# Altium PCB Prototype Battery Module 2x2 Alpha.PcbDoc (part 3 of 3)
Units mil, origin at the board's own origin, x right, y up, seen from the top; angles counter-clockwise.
Board outline 659.45 x 1614.17 mil, 6 copper layers (Component Side, Ground Plane (GND), Inner Layer 1, Inner Layer 2, Power Plane (VCC), Solder Side), stack 51.068 mil thick; 192 components, 101 nets, 859 pads, 497 vias.
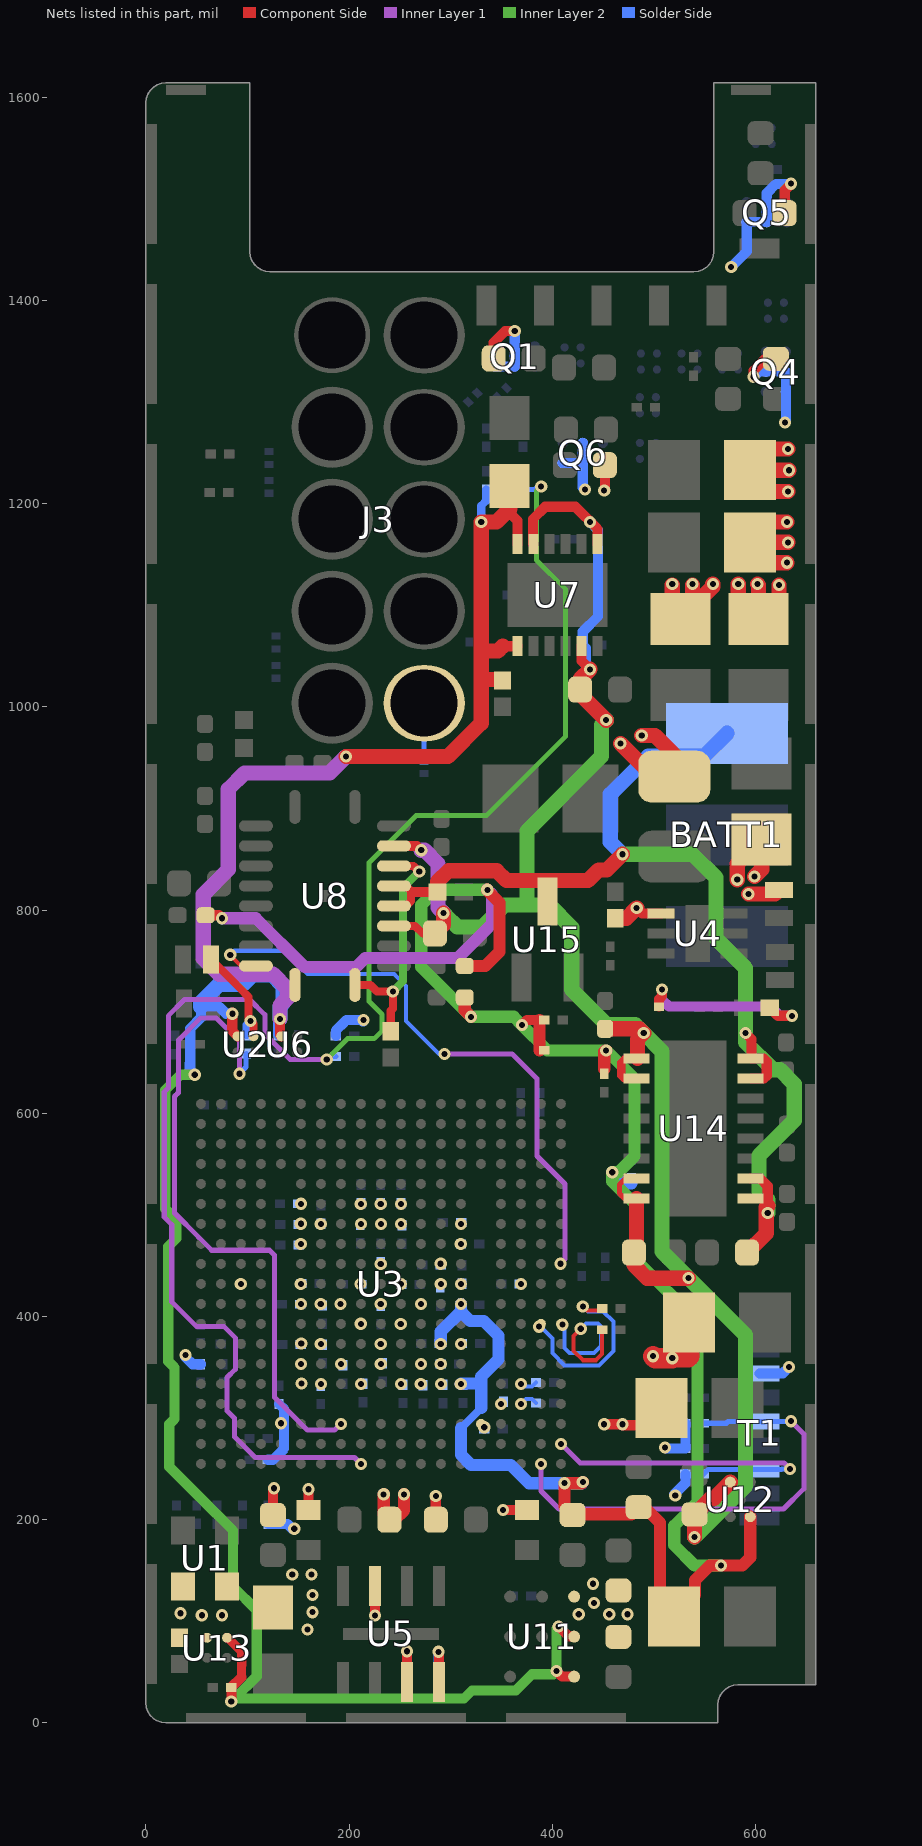
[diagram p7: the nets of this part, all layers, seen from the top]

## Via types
v1: diameter 12, hole 6, Component Side to Solder Side, tented both sides, 490 vias
v2: diameter 19.68, hole 10, Component Side to Solder Side, 6 vias
v3: diameter 12, hole 6, Component Side to Solder Side, 1 vias

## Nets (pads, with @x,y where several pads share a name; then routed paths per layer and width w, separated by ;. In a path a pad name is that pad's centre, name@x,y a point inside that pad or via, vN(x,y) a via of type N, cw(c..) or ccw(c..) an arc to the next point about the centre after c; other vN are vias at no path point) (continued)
TDO: R29.2 T1.6 U3.B1 | length 323
  Inner Layer 1 w5: v1(408.43,274.68) 427.11,256 628,256 v1(634,250)
  Solder Side w5: R29.2@549.06,245 553.62,249.57 625.57,249.57 625.57,249.43 626.13,250 v1(634,250)
TMS: R27.2 T1.4 U3.A2 | length 475.2
  Inner Layer 1 w5: v1(388.74,255) 388.74,228.26 406.5,210.5 511,210.5 ; 526.59,210.5 511,210.5 ; v1(635,297) 647.5,284.5 647.5,230.5 627.5,210.5 511,210.5
  Solder Side w5: R27.2@549.06,295 571.19,295 573,296.81 T1.4@604,296.81 634.81,296.81 v1(635,297)
TX_CLK_N: C86.2 U3.H2 | length 191.6
  Component Side w4: v1(430,410) 434,406 443,406 ; C86.2@444.95,406 443,406 ; C86.2@448.94,408 446.95,406 443,406
  Solder Side w4: v1(387,390) 388.38,390 400,378.38 400,364 412,352 446,352 460,366 460,395 450,405 436,405 435,405 v1(430,410)
TX_CLK_P: C85.2 U3.H1 | length 190.3
  Component Side w4: v1(428,388) 421,381 421,366 430,357 443,357 448.94,362.94 C85.2@448.94,387
  Solder Side w4: v1(410,392) 412,390 412,368.97 416.97,364 441.03,364 448,370.97 448,390.03 445.03,393 433,393 v1(428,388)
TX_N: C84.2 U3.E3 | length 17.7
  Solder Side w4: v1(369.06,333.74) 371.8,331 379.94,331 C84.2@383.94,335
TX_P: C83.2 U3.D3 | length 18.6
  Solder Side w4: v1(369.06,314.06) 374,319 379.95,319 C83.2@383.94,315
USBPG_N: U3.L1 U8.19 | length 599.1
  Component Side w4: v1@84.17,754.29 93.38,745.08 U8.19@108.26,745.08
  Inner Layer 1 w5: v1(294,658.51) 360.49,658.51 384.93,634.07 384.93,558 412.5,530.43 412.5,456.5 v1(408,452)
  Solder Side w4: v1(83,756) 87,760 136,760 159,737 244.38,737 256,725.38 256,718 256,691 288.49,658.51 v1(294,658.51)
V1P2: C1.2 C2.2 C18.2 C19.2 C20.2 C21.2 C22.2 C23.2 C24.2 C25.2 C27.2 C28.2 C29.2 C30.2 C33.2 C40.2 C41.2 C78.2 U3.E8 U3.E14 U3.F7 U3.G6 U3.G10 U3.G14 U3.H9 U3.H11 U3.J8 U3.J10 U3.J12 U3.K9 U3.K11 U3.L10 U3.M6 U3.N9 U3.N10 U3.N11 U3.N14 U3.P9 U3.P10 U3.P11 U11.A1 | length 71.1
  Component Side w10: U3.E14@152.52,333.74 152.74,333.74 v1(153,334)
  Component Side w20: v1(499,361) 501,359 v1(518,359) 519,360 534,360 534.6,360.6 C78.2@534.6,394
  other v1: 426,107 456,107 474,107 441,118 440,137 270.55,333.48 290.19,353.35 152.89,373.49 231.09,372.94 310,373.03 211.5,392.84 250.82,392.72 191.63,412.4 231.14,412.44 270.59,412.44 211.24,432.09 250.95,432.09 231.09,451.86 309.91,471.44 152.44,491.29 211.57,491.22 231.26,491.22 250.94,491.22 211.5,510.84 231.09,510.91 250.98,510.83
V2P5: C59.2 C63.2 C64.2 C65.2 C82.2 L5.2 R38.1 R40.1 R42.1 R50.1 R51.1 R53.1 R54.1 U3.E6 U3.G7 U3.J6 U12.C3 | length 2340.7
  Component Side w10: R38.1@58.78,795 72,795 v1(75,792) ; v1(370,687) 375,692 R51.1@387.22,692
  Component Side w12: R42.1@313.78,714 313.78,701.22 v1(320,695) ; R40.1@313.78,745 334,745 348,759 348,807.27 336,819.27 v1(336,820) ; R50.1@387.22,662 R51.1@387.22,692 ; C59.2@420,204.69 412,212.69 v1(412,236) 429,236 v1(430,237) ; C59.2@420.67,205.35 478.04,205.35 C82.2@485,212.31 490.69,212.31 506,197 506,118.6 L5.2@519.6,105 540.5,125.9 540.5,140.5 555,155 v1(566,155) 587,155 594.84,162.84 U12.C3@594.84,202.95 ; R54.1@451,643.78 451,660.64 452.36,662 v1(453,662)
  Inner Layer 1 w12: v1(75,792) 108,792 156,744 207,744 215.82,752.82 306.82,752.82 340.69,786.68 340.69,815.32 v1(336,820)
  Inner Layer 2 w12: v1(336,820) 286,820 271,805 271,744 v1(320,695) 362,695 v1(370,687) 395,662 v1(453,662) 481,634 481,557.96 465.04,542 v1(459,542) 459,533 483,509 483,455 543,395 543,359 ; 520,182.91 520,175 ; 543,387 543,359 ; v1(566,155) 540,155 520,175 ; 520,175 520,194 543,217 543,359
  Solder Side w8: 310,290 330,310
  Solder Side w12: v1(290.19,373.03) 290.19,385.18 310.06,405.06 ; v1(309.92,333.61) 310.31,334 330,334 ; 310,290 310,264 320,254 359,254 377,236 v1(412,236) v1@429,236 ; v1(310.06,412.4) 310.06,405.06 ; 330,310 330,334 ; v1(459,542) 469.78,531.22 R53.1@478,531.22 ; 310.06,405.06 312.11,403 312.11,402.63 319.22,395.52 332.52,395.52 347,381.04 347,358 330,341 330,334
V3P3: C3.2 C4.2 C5.2 C6.2 C7.2 C9.2 C12.1 C13.1 C15.1 C16.2 C17.1 C26.2 C34.2 C35.2 C36.2 C37.2 C38.2 C44.2 C51.2 C57.2 C58.2 C60.2 C61.2 C62.2 C66.2 C67.2 C68.2 C69.2 C70.2 C71.2 C72.2 C73.2 C95.2 L2.1 R22.1 R26.2 R27.1 R28.1 R29.1 R34.2 T1.2 U1.1 U1.4 U3.C5 U3.C15 U3.D4 U3.E7 U3.E9 U3.E11 U3.E13 U3.F8 U3.F10 U3.F12 U3.F14 U3.G13 U3.J13 U3.J14 U3.K3 U3.K6 U3.K7 U3.K14 U3.K17 U3.L7 U3.M14 U3.N6 U3.N13 U3.P14 U4.4 U5.3 U5.7 U5.8 U13.A1 | length 788.9
  Component Side w10: C60.2@125,204.69 125,231 v1(126,231) ; U3.C15@132.83,294.37 132.83,294.83 v1(133,295) ; C16.2@160,209.68 v1(160,230) ; v1(225.39,105.61) U5.3@225.39,134.84 ; U5.7@256.89,40.35 v1(256.89,70.58) ; C72.2@285.31,200 v1(285.31,223.31) ; v1(288,70) 288.39,69.61 U5.8@288.39,40.35 ; v1(351.32,209.68) C37.2@375,209.68 ; v1(451,294) v1(469,294) 469,293 490.6,293 C38.2@507.6,310 ; v1(483,802) 488.32,796.68 U4.4@507.17,796.68
  Component Side w12: v1(234,225) 234,205.69 C61.2@239.69,200 245,200 254,209 v1(254,225)
  Component Side w15: C9.2@462,792.01 473.01,792.01 v1(483,802) ; v1(467,964) 499.63,931.37 L2.1@520,931.37 520,953 501,972 v1(488,972)
  Solder Side w10: v1(39,362) 39,360 45.94,353.06 R34.2@54,353.06 ; R26.2@120,195.94 139.06,195.94 143.84,191.16 v1(146,191.16) ; R22.1@120.06,259 125,259 136,270 136,308.94 C34.2@131,313.94 ; C3.2@186.94,676 186.94,681.48 ; 195.23,689.77 186.94,681.48 ; v1@213.34,690.33 214,690.33 v1(214,692) 197.46,692 186.94,681.48 ; v1(256.89,70.58) 257,70.47 C13.1@257,55.06 ; C12.1@288,55.06 v1(288,70) ; v1(511,271) 512,270 R28.1@530.94,270 R27.1@530.94,295 ; v1(521,224) 520,225 530.94,235.94 R29.1@530.94,245 ; T1.2@604,344.06 626.8,344.06 v1(633,350.25)
  other v1: 159,92 55,106 75,106 34,108 164,109 164,126 144,146 163,146 333,291 349.37,314.06 172.2,333.74 211.57,333.74 250.94,333.74 290.32,333.74 152.52,353.43 191.89,353.43 231.18,353.35 270.63,353.43 172.13,372.97 152.48,412.44 172.09,412.43 93.39,432.09 152.45,432.09 290.24,432.08 310.07,431.94 369.06,432.17 290.09,451.91 152.46,471.44 172.13,490.97 310.09,490.97 152.56,510.94
V3P3_ALWAYS: C32.2 C39.2 C52.2 C77.2 C94.2 R3.2 U2.A2 U6.A2 U7.1 U7.12 U11.A2 U11.A3 U13.A2 | length 2532.4
  Component Side w9: U13.A2@79.84,83.84 80.55,83.84 94.26,70.13 94.26,56.74 94,56.47 94,44.95
  Component Side w10: v1(84,21) 84.06,21.06 C94.2@84.06,35 94,44.95 ; v1@85,699 v1(85,698) 85,681 U2.A2@90.13,675.87 86,680 ; v1(132,693) 132,677 U6.A2@133.13,675.87 ; 351,1060 351.2,1059.8 U7.1@365.63,1059.8 ; C52.2@358,1217.54 358,1195 358,1191 365.63,1183.37 U7.12@365.63,1160.2 ; v1(404,51) 409.37,45.63 U11.A3@421.5,45.63 ; v1(406,95) 416,85 U11.A2@421.5,85
  Component Side w15: v1(197,951.2) 297.2,951.2 330,984 330,1027 ; C77.2@351,1025.99 349.99,1027 330,1027 ; 351.2,1059.8 346.39,1055 330,1055 ; 358,1195 345,1182 v1(330,1182) 330,1055 ; 330,1027 330,1055
  Inner Layer 1 w15: 114,737 102,737 ; v1(132,693) 132,706 139,713 139,723 125,737 102,737 ; v1(197,951.2) 180.81,935 97,935 81,919 81,840 56.5,815.5 56.5,752.5 72,737 102,737
  Inner Layer 2 w10: 19,597 19,584 ; 23.5,251.82 26,249.32 ; v1@45.99,638 v1(48,638) 34,638 19,623 19,584 ; 59.65,215.58 53.62,221.62 ; v1(84,21) v1@87,24 ; 109,72 109,46 ; v1(406,95) 404,93 v1(404,51) 401,48 380,48 364,32 321,32 313,24 v1@87,24 ; 19,584 19,506 30,495 30,477 22,469 22,356 28.02,349.98 28.02,299 23,293.98 23,252.23 53.62,221.62 ; 53.62,221.62 85.69,189.55 85.69,134.32 109,111 109,46 ; v1@87,24 109,46
  Solder Side w8: v1(330,1182) 330,1198 335,1203 R3.2@335,1213.94
  Solder Side w10: 43,649 43,643 ; v1(48,638) 43,643 ; v1(85,698) 79,698 72,705 C32.2@54.06,705 54.06,694.06 43.54,683.54 43.54,643.54 43,643 ; C39.2@130,677.06 v1@130,691 ; v1(132,693) v1@132,696.63
  Solder Side w15: C32.2@54.06,705 54.06,709.06 71.79,726.79 95.56,726.79 105.28,736.5 123.99,736.5 ; 128.25,732.25 123.99,736.5 ; v1(132,693) 132,705 135,708 135,725.49 123.99,736.5
V28P0: C8.2 C10.2 C11.2 C31.2 C49.2 C53.2 D1.2 Q1.2 Q1.3 Q1.6 Q4.2 Q4.3 Q4.6 Q5.2 Q5.3 Q5.6 Q6.2 Q6.3 Q6.6 R11.1 R13.1 R16.1 R17.1 R44.1 | length 1278.7
  Component Side w10: R11.1@342.32,1343 342.32,1358.65 353.67,1370 v1(363,1370) ; v1(451,1213) 451.69,1213.68 R17.1@451.69,1238 ; R13.1@504.94,705 504.94,712.32 508,715.37 v1(508,722) ; v1(598,1325) 598,1331 609.69,1342.68 R44.1@620,1342.68 ; C10.2@613.99,704 621.99,696 v1(636,696) ; R16.1@628.69,1486 628.69,1508.68 v1(635,1515)
  Component Side w15: v1@518,1119.97 518,1094.4 C31.2@526,1086.4 C31.2@538,1098.4 ; v1@538,1119.97 C31.2@538,1098.4 ; v1(558,1121) 558,1118.4 C31.2@538,1098.4 ; v1(582,830) 582,845.6 C49.2@606,869.6 606,840 v1(599,833) ; v1(583,1121) 583,1106.4 C53.2@603,1086.4 ; v1@597,816 v1(593,816) 619.22,816 D1.2@623,819.78 ; v1(602,1121) 603,1120 C53.2@603,1086.4 ; v1(623,1120) 623,1106.4 C53.2@603,1086.4 ; v1(631,1142) 614.4,1142 C8.2@594.4,1162 ; v1(631,1182) 605,1182 594.4,1171.4 C8.2@594.4,1162 ; v1(632,1162) C8.2@594.4,1162 ; v1(632,1212) 614,1212 594.4,1231.6 C11.2@594.4,1233 ; v1(632,1254) 615.4,1254 C11.2@594.4,1233 ; v1(633,1233) C11.2@594.4,1233
  Inner Layer 1 w10: v1(508,722) 508,712 515,705 615,705 ; 623,697 615,705 ; v1(636,696) 624,696 615,705
  Solder Side w10: Q1.2@343.32,1335.16 Q1.3@363,1335.16 363,1337 Q1.6@363,1354.84 363,1364 v1(363,1370) ; Q6.2@410.32,1240.16 Q6.3@430,1240.16 ; Q6.6@430,1259.84 Q6.3@430,1240.16 ; v1(432,1214) 430,1216 Q6.3@430,1240.16 ; v3(576,1433) 591.32,1448.32 Q5.2@591.32,1477.16 602,1477.16 Q5.3@611,1477.16 Q5.6@611,1496.84 611,1505.67 620,1514.67 634.67,1514.67 v1(635,1515) ; v1(598,1325) 603,1330 Q4.6@610.16,1330 Q4.3@629.84,1330 Q4.2@629.84,1310.32 629.84,1283.16 630,1283 630,1281 v1(628.98,1280.02) v1@629,1281
  other v1: 518,1121 538,1121
VBATT: BATT1.1 C46.2 C47.2 U8.5 U8.6 U14.1 U14.2 U14.7 U14.8 U15.3 | length 1141.3
  Component Side w8: U8.5@244.09,804.14 256.14,804.14 260.82,808.82 260.82,817 261.82,818 256,823.82 U8.6@244.09,823.82
  Component Side w10: 261.82,818 C46.2@287.01,818 ; v1(590,679) 596.1,672.9 596.1,653.9 608.1,653.9 611,651 611,637 608.21,634.21 U14.7@596.1,634.21 ; U14.2@595.1,535.79 604.59,535.79 612,528.37 612,509
  Component Side w15: C46.2@287.01,818 287.01,828.01 297.77,838.77 345.23,838.77 354.91,829.09 435.17,829.09 445.62,839.55 453.55,839.55 v1(469,855) ; C47.2@591.69,463 610.63,481.94 610.63,507.63 612,509
  Inner Layer 2 w15: v1(469,855) 538,855 561,832 561,772 590,743 v1(590,679) 590,670 617,643 624,643 638,629 638,593 603.5,558.5 603.5,523.5 612,515 v1(612,502)
  Solder Side w15: v1(469,855) 457,867 457,914 494.5,951.5 549.31,951.5 BATT1.1@571.81,974
VCONN: C42.2 C48.2 C50.2 C81.2 J3.1 R39.1 R49.1 TVS9.1 U7.5 U7.7 U7.11 U8.4 U8.8 U12.A1 U14.9 U14.10 U14.15 U14.16 | length 2085.3
  Component Side w5: U14.16@482.9,516.1 470.9,516.1 466,521 466,529.91 471.88,535.79 U14.15@482.9,535.79
  Component Side w8: U8.4@244.09,784.45 265,784.45 272.45,777 C42.2@284.31,777 ; 468,650 467.87,649.87 ; U14.10@482.9,634.21 470.79,634.21 467.87,637.13 467.87,649.87 ; U14.9@482.9,653.9 471.9,653.9 467.87,649.87
  Component Side w10: U8.8@244.09,863.19 266.81,863.19 v1(271,859) ; U7.11@381.38,1160.2 381,1160.57 381,1185.05 392.95,1197 422.63,1197 444.37,1175.26 U7.7@444.37,1160.2 ; C50.2@427.31,1017 C50.2@428.62,1018.31 ; U7.5@428.62,1059.8 428.62,1045.38 v1(437,1037)
  Component Side w15: C42.2@284.77,777 C42.2@284.31,777 293,785.69 v1(293,797) ; v1(437,1037) 427.31,1027.31 C50.2@427.31,1017 427.31,1012.69 v1(453,987) ; R49.1@452,683.22 485.78,683.22 v1(490,679) 483.9,672.9 U14.9@483.9,653.9 ; U14.16@482.9,516.1 482.9,465.58 C48.2@480.31,463 480.31,450.69 493.3,437.7 519,437.7 ; 506.16,437.7 519,437.7 ; v1(534,438) 533.51,438 533.21,437.7 519,437.7 ; v1(540,183) C81.2@540,205.31 555.84,221.16 559.27,221.16 U12.A1@575.16,237.05
  Inner Layer 1 w15: v1(271,859) 274.16,859 287.5,845.66 287.5,802.5 v1(293,797)
  Inner Layer 2 w15: v1@294.58,795.42 306.5,783.5 331.35,783.5 ; 316.02,783.5 331.35,783.5 ; 336.42,788.58 331.35,783.5 ; 419,767.5 419,738 ; v1(453,987) 448.5,982.5 448.5,951.5 375,878 375,805 ; v1(540,183) 590,233 590,382 v1(534,438) 508,464 508,661 v1(490,679) 481.5,687.5 453.5,687.5 419,722 419,738 ; 331.35,783.5 352.85,805 375,805 ; 375,805 397,805 419,783 419,738
  Solder Side w5: TVS9.1@273.86,946.14 J3.1@273.86,1003.7
  Solder Side w10: v1(437,1037) 432.94,1041.06 432.94,1058.01 R39.1@429.94,1061 429.94,1073.94 445,1089 445,1174 v1(437,1182)
VLDO: C45.2 U8.1 U8.7 | length 232.9
  Component Side w8: U8.1@205.71,726.38 221,726.38 227.38,720 v1(243,720) 243,703 ; C45.2@241,680.99 241,701 ; U8.7@244.09,843.51 263.49,843.51 v1(269,838)
  Inner Layer 2 w8: v1(243,720) 253,730 253,822 v1(269,838)
VUSB: U8.20
WAKE_RX: R7.2 U3.C12 | length 683.1
  Inner Layer 1 w5: 28,616 28,606 ; 30.59,619.06 32,620.47 32,646 ; 31.76,620.24 28,616.47 28,606 ; 32,641.77 32,646 ; 58.46,471.54 52,478 ; 70,693 91,672 ; 74.21,688.79 69,694 62,694 54,694 32,672 32,646 ; 86.37,676.63 92,671 v1(92,639) ; v1(191.89,294.37) 185.7,288.18 158.91,288.18 126.65,320.44 126.65,460.35 121.73,465.27 64.73,465.27 52,478 ; 28,606 28,600 28,594 28,502 52,478
  Solder Side w5: v1(92,639) 98.5,645.5 98.5,651 ; 98.5,647.5 98.5,651 ; R7.2@99,658.94 98.5,658.45 98.5,651
WAKE_RX_PWR: D3.1 R7.1 U2.B2 | length 111.5
  Component Side w8: D3.1@63.98,751.61 92.87,722.72 101,714.59 v1@101,693 ; v1(103,691) v1@101,693 ; U2.B2@105.87,675.87 105.87,688.13 v1@101,693
  Solder Side w8: R7.1@99,677.06 99,683 99,687 v1(103,691)
WAKE_TX: R2.2 R4.2 U3.A11 | length 1613.3
  Inner Layer 1 w5: 19.5,496.36 18,497.86 ; 57,712 38,712 ; 117,687 117,684 ; v1@177.04,653.04 v1(178,653.04) 141.96,653.04 117,678 117,684 ; v1(211.57,255) 205.39,261.18 107.67,261.18 87.2,281.66 87.2,299.88 79.89,307.2 79.89,339.89 88,348 88,379 77,390 50,390 25.43,414.57 25.43,490.43 18,497.86 ; 18,497.86 18,621 22,625 22,696 38,712 ; 38,712 102,712 117,697 117,684
  Inner Layer 2 w5: v1@178.46,653.5 v1(178,653.04) 198.46,673.5 219,673.5 ; 215.5,673.5 219,673.5 ; v1(389,1217) 384.5,1212.5 384.5,1144.5 413.15,1115.85 413.15,1048 ; 413.15,1035.85 413.15,1048 ; 219,673.5 224.59,673.5 232.5,681.41 232.5,697.27 219.5,710.27 219.5,846.64 265.86,893 335,893 413.15,971.15 413.15,1048
  Solder Side w5: v1(178,653.04) 180.96,656 R2.2@186.94,656 ; R4.2@371,1213.94 382.94,1213.94 386,1217 v1(389,1217)
pads on no net: U3.A3 U3.A4 U3.A5 U3.A6 U3.A7 U3.A8 U3.A9 U3.A12 U3.A13 U3.A14 U3.A15 U3.A16 U3.A17 U3.B3 U3.B4 U3.B5 U3.B6 U3.B7 U3.B8 U3.B9 U3.B10 U3.B11 U3.B12 U3.B14 U3.B15 U3.B16 U3.B17 U3.C2 U3.C6 U3.C7 U3.C8 U3.C9 U3.C10 U3.C11 U3.C14 U3.D1 U3.D2 U3.D18 U3.E1 U3.E2 U3.E17 U3.E18 U3.F1 U3.F3 U3.F17 U3.F19 U3.G1 U3.G17 U3.H3 U3.H7 U3.H14 U3.H17 U3.H18 U3.H19 U3.J2 U3.J17 U3.J18 U3.K18 U3.L3 U3.L6 U3.L14 U3.L18 U3.L19 U3.M7 U3.M13 U3.M17 U3.M18 U3.M19 U3.N17 U3.N19 U3.P3 U3.P6 U3.R1 U3.R2 U3.R3 U3.T1 U3.T2 U3.T3 U3.T10 U3.T19 U3.U1 U3.U2 U3.U10 U3.U18 U3.U19 U3.V1 U3.V2 U3.V6 U3.V7 U3.V8 U3.V9 U3.V12 U3.V13 U3.V14 U3.V15 U3.W2 U3.W5 U3.W6 U3.W8 U3.W9 U3.W11 U3.W12 U3.W14 U3.W15 U4.2 U4.5 U7.8

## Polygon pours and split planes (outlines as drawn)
V1P2 on Component Side "TopLayer-No Net" (solid, remove dead copper, pour order 17): 514,424 560,424 562,422 562,385 562,367 558,363 544,349 509,349 496,349 489,356 488,357 488,369 488,370 490,372 492,374 504,374 505,374 510,379 510,408 510,420 514,424
GND on Component Side "TopLayer-No Net" (solid, remove dead copper, pour order 16): 587,445 624,445 631,438 631,401 631,368 624,361 612,349 612,302 612,284 607,279 559,279 557,279 555,281 554,282 554,344 568,358 575,365 575,376 575,438 579,442 582,445 587,445
V3P3 on Component Side "TopLayer-No Net" (solid, remove dead copper, pour order 15): 475,342 507,342 531,342 535,338 535,297 535,283 532,280 531,279 469,279 451,279 443,287 441,289 441,305 441,321 448,328 462,342 475,342
V1P2 on Component Side "Mechanical 1-No Net" (solid, pour order 14): 415,116 415,104 419,100 420,99 439,99 444,94 444,84 444,78 449,73 481,73 485,77 485,138 481,142 478,145 422,145 418,145 415,142 415,116
GND on Component Side "Mechanical 1-No Net" (solid, pour order 13): 105,68 109,72 155,72 166,72 171,67 171,28 166,23 106,23 104,25 104,67 105,68
GND on Component Side "Mechanical 1-No Net" (solid, pour order 12): 336,31 365,31 372,38 372,111 372,149 380,157 402,157 407,157 410,154 472,154 477,159 481,163 481,183 476,188 456,188 442,188 434,180 433,179 412,179 356,179 350,173 334,157 334,112 334,33 336,31
V3P3 on Component Side "Top Solder-No Net" (solid, remove dead copper, pour order 11): 68,76 66,74 23,74 23,148 26,151 169,151 175,145 175,93 167,85 110,85 102,93 99,96 81,96 73,96 68,91
V1P2 on Inner Layer 2 "TopLayer-No Net" (solid, remove dead copper, pour order 18): 393,525 525.09,392.91 525.09,99.21 517.6,91.72 416.28,91.72 308,200 261,200 120,341 120,489 156,525
VCONN on Inner Layer 1 "Inner Layer 1-No Net" (solid, pour order 10): 230,963 230,1026 251,1047 372,1047 400,1075 456,1075 494,1037 494,945 492,945 474,927 445,898 399,898 388,898 350,936 344,942 264,942 251,942 230,963
GND on Ground Plane (GND) (split plane): 649.36,47.49 582.68,47.49 582.11,47.41 581.55,47.42 577.17,46.93 576.07,46.66 574.97,46.43 570.8,44.97 569.8,44.46 568.77,43.99 565.04,41.65 564.17,40.93 563.27,40.24 560.15,37.12 559.47,36.23 558.75,35.36 556.4,31.62 555.93,30.6 555.42,29.59 553.97,25.43 553.73,24.32 553.46,23.23 552.97,18.85 552.98,18.28 552.91,17.72 552.91,10.09 20.25,10.09 17.56,10.39 15.55,11.09 13.74,12.23 12.23,13.74 11.09,15.55 10.39,17.56 10.09,20.25 10.09,1593.92 10.39,1596.61 11.09,1598.62 12.23,1600.43 13.74,1601.94 15.55,1603.08 17.56,1603.78 20.25,1604.09 92.28,1604.09 92.28,1448.03 92.35,1447.47 92.34,1446.9 92.83,1442.52 93.1,1441.43 93.34,1440.32 94.79,1436.16 95.3,1435.15 95.77,1434.12 98.12,1430.39 98.84,1429.52 99.52,1428.63 102.64,1425.51 103.54,1424.82 104.41,1424.1 108.14,1421.76 109.17,1421.28 110.18,1420.78 114.34,1419.32 115.44,1419.09 116.54,1418.82 120.92,1418.32 121.48,1418.33 122.05,1418.26 539.37,1418.26 539.93,1418.33 540.5,1418.32 544.88,1418.82 545.98,1419.09 547.08,1419.32 551.24,1420.78 552.25,1421.28 553.28,1421.76 557.01,1424.1 557.88,1424.82 558.78,1425.51 561.89,1428.63 562.58,1429.52 563.3,1430.39 565.65,1434.12 566.12,1435.15 566.63,1436.16 568.08,1440.32 568.31,1441.42 568.58,1442.52 569.08,1446.9 569.07,1447.47 569.14,1448.03 569.14,1604.09 649.36,1604.09
V28P0 on Power Plane (VCC) (split plane): 649.36,684.97 648.45,685.09 559.18,685.09 494.99,749.27 495.09,750 495.09,755.82 517.13,777.87 518.74,779.96 519.74,782.39 520.09,785 520.09,795 520.09,980 519.74,982.61 518.74,985.04 517.13,987.13 445.09,1059.18 445.09,1135 444.74,1137.61 443.74,1140.04 442.13,1142.13 400.09,1184.18 400.09,1280 399.74,1282.61 399.24,1283.83 398.74,1285.04 397.13,1287.13 335.09,1349.18 335.09,1355 334.74,1357.61 334.09,1359.2 334.09,1418.26 539.37,1418.26 539.93,1418.33 540.5,1418.32 544.88,1418.82 545.98,1419.09 547.08,1419.32 551.24,1420.78 552.25,1421.28 553.28,1421.76 557.01,1424.1 557.88,1424.82 558.78,1425.51 561.89,1428.63 562.58,1429.52 563.3,1430.39 565.65,1434.12 566.12,1435.15 566.63,1436.16 568.08,1440.32 568.31,1441.42 568.58,1442.52 569.08,1446.9 569.07,1447.47 569.14,1448.03 569.14,1604.09 649.36,1604.09
V3P3 on Power Plane (VCC) (split plane): 92.28,1448.03 92.35,1447.47 92.34,1446.9 92.83,1442.52 93.1,1441.43 93.34,1440.32 94.79,1436.16 95.3,1435.15 95.77,1434.12 98.12,1430.39 98.84,1429.52 99.52,1428.63 102.64,1425.51 103.54,1424.82 104.41,1424.1 108.14,1421.76 109.17,1421.28 110.18,1420.78 114.34,1419.32 115.44,1419.09 116.54,1418.82 120.92,1418.32 121.48,1418.33 122.05,1418.26 313.91,1418.26 313.91,1346 314.26,1343.39 315.27,1340.96 316.87,1338.87 317.43,1338.43 317.87,1337.87 379.91,1275.82 379.91,1180 380.26,1177.39 381.27,1174.96 382.87,1172.87 424.91,1130.82 424.91,1055 425.26,1052.39 426.27,1049.96 427.87,1047.87 499.91,975.82 499.91,795 499.91,789.18 487.87,777.13 479.83,769.1 478.96,768.74 476.87,767.13 475.27,765.04 474.26,762.61 473.91,760 473.91,746 474.26,743.39 475.27,740.96 476.87,738.87 547.87,667.87 549.96,666.26 550.67,665.97 552.39,665.26 555,664.91 644.27,664.91 649.36,659.82 649.36,47.49 582.68,47.49 582.11,47.41 581.55,47.42 577.17,46.93 576.07,46.66 574.97,46.43 570.8,44.97 569.8,44.46 568.77,43.99 565.04,41.65 564.17,40.93 563.27,40.24 560.15,37.12 559.47,36.23 558.75,35.36 556.4,31.62 555.93,30.6 555.42,29.59 553.97,25.43 553.73,24.32 553.46,23.23 552.97,18.85 552.98,18.28 552.91,17.72 552.91,10.09 20.25,10.09 17.56,10.39 15.55,11.09 13.74,12.23 12.23,13.74 11.09,15.55 10.39,17.56 10.09,20.25 10.09,1593.92 10.39,1596.61 11.09,1598.62 12.23,1600.43 13.74,1601.94 15.55,1603.08 17.56,1603.78 20.25,1604.09 92.28,1604.09

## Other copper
Component Side:
  text "Top" at 177.17,-433.07 h60
Inner Layer 1:
  text "SIG1_LAYER3" at 0,-413.39 h60
Inner Layer 2:
  text "SIG2_LAYER4" at -39.37,-393.7 h60
Solder Side:
  text "Bottom" at 137.8,-452.76 h60
Ground Plane (GND) (plane layer: these items are gaps in the copper):
  text "GND_LAYER2" at -39.37,-374.02 h60
Power Plane (VCC) (plane layer: these items are gaps in the copper):
  lines w20: 324,1346 324,1428.35 ; 325,1355 325,1345 390,1280 390,1180 435,1135 435,1055 510,980 510,795 510,785 ; 484,760 484,746 555,675 648.45,675 658.45,665 ; 485,750 485,760 510,785 ; 495,770 510,785
  text "PWR_LAYER5" at -19.68,-433.07 h60

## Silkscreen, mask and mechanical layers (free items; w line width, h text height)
Top Overlay:
  text "Bat Module" at 66,1302 h30 r90
  text "M" at 107,1079 h100 r90
  text "K" at 599,819 h8
  text "A" at 595,786 h14
  text "K" at 34,769 h8
  text "K" at 597,756 h8
  text "A" at 76,734 h14
  text "A" at 595,722 h14
  text "A" at 78,708 h14
  text "K" at 15,679 h8
  text "Top Overlay" at -19.68,-433.07 h14
Bottom Overlay:
  text "(C) Motorola 2014" at 43,1584 h30 r90
  text "+" at 414,985 h30 r90
  text "-" at 414,889.5 h30 r90
  text "T" at 414,794 h30 r90
  text "Bottom Overlay" at -118.11,-433.07 h60
Top Paste:
  text "Top Paste" at -39.37,-413.39 h60
Bottom Paste:
  text "Bottom Paste" at -59.06,-433.07 h60
Top Solder:
  text "Top Solder" at 0,-374.02 h60
Bottom Solder:
  text "Bottom Solder" at -59.06,-452.76 h60
DIMENSION:
  lines w1: -0.01,19.69 ccw(c19.68,19.69) 19.68,0.01 ; 102.35,1450.4 ccw(c122.04,1450.4) 122.04,1430.72 ; 489.36,1430.72 ccw(c489.36,1450.4) 509.05,1450.4 ; 512.98,17.72 cw(c532.67,17.72) 532.67,37.41
OUTLINE:
  lines w1: 539.32,1428.32 ccw(c539.32,1448) 559,1448 ; 539.44,1428.35 122.04,1428.35 cw(c122.04,1448.03) 102.35,1448.03 102.35,1614.18 19.68,1614.18 ccw(c19.68,1594.5) -0.01,1594.5 -0.01,19.69 ccw(c19.68,19.69) 19.68,0.01 562.99,0.01 562.99,17.72 cw(c582.68,17.72) 582.68,37.41 659.45,37.41 659.45,1614.17 559.06,1614.17 559.06,1448.03
Mechanical 4:
  region: 615.16,1603.35 574.8,1603.35 574.8,1613.19 615.16,1613.19
  region: 59.06,1603.35 18.7,1603.35 18.7,1613.19 59.06,1613.19
  region: 0.98,39.37 0.98,157.48 10.83,157.48 10.83,39.37
  region: 0.98,196.85 0.98,314.96 10.83,314.96 10.83,196.85
  region: 0.98,354.33 0.98,472.44 10.83,472.44 10.83,354.33
  region: 0.98,511.81 0.98,629.92 10.83,629.92 10.83,511.81
  region: 0.98,669.29 0.98,787.4 10.83,787.4 10.83,669.29
  region: 0.98,826.77 0.98,944.88 10.83,944.88 10.83,826.77
  region: 0.98,984.25 0.98,1102.36 10.83,1102.36 10.83,984.25
  region: 0.98,1141.73 0.98,1259.84 10.83,1259.84 10.83,1141.73
  region: 0.98,1299.21 0.98,1417.32 10.83,1417.32 10.83,1299.21
  region: 0.98,1456.69 0.98,1574.8 10.83,1574.8 10.83,1456.69
  region: 648.62,1456.69 648.62,1574.8 658.46,1574.8 658.46,1456.69
  region: 648.62,1299.21 648.62,1417.32 658.46,1417.32 658.46,1299.21
  region: 648.62,1141.73 648.62,1259.84 658.46,1259.84 658.46,1141.73
  region: 648.62,984.25 648.62,1102.36 658.46,1102.36 658.46,984.25
  region: 648.62,826.77 648.62,944.88 658.46,944.88 658.46,826.77
  region: 648.62,669.29 648.62,787.4 658.46,787.4 658.46,669.29
  region: 648.62,511.81 648.62,629.92 658.46,629.92 658.46,511.81
  region: 648.62,354.33 648.62,472.44 658.46,472.44 658.46,354.33
  region: 648.62,196.85 648.62,314.96 658.46,314.96 658.46,196.85
  region: 648.62,39.37 648.62,157.48 658.46,157.48 658.46,39.37
  region: 354.33,10.83 472.44,10.83 472.44,0.98 354.33,0.98
  region: 196.85,10.83 314.96,10.83 314.96,0.98 196.85,0.98
  region: 39.37,10.83 157.48,10.83 157.48,0.98 39.37,0.98
ASSY_TOP:
  text "ASSY TOP" at 11,-291 h60
ASSY_BOT:
  text "ASSY BOTTOM" at 611,-291 h60
Drill Drawing:
  lines w1: -87.31,0.01 -0.01,0.01 -0.01,-91.17 ; 102.35,1614.18 102.35,1658.11 ; 496.06,1428.35 708.66,1428.35 ; 559.05,1613.18 559.05,1653.17 ; 562.99,-43.92 562.99,0.01 ; 593.06,1614.17 708.66,1614.17 ; 609.44,37.41 658.9,37.41 ; 609.44,1614.18 634.78,1614.18 ; 650.69,37.4 737.99,37.4 ; 659.45,-8.49 659.45,37.41 ; -185.05,1712.61 -296.71,1712.61 -185.05,1712.61 ; -185.05,1712.61 2.41,1603.94 ; -185.05,1712.61 2.41,1603.94 ; -146.18,1661.63 -121.5,1704.21 ; -146.18,1661.63 2.41,1603.94 ; -146.18,1661.63 -121.5,1704.21 ; -146.18,1661.63 2.41,1603.94 ; -121.5,1704.21 2.41,1603.94 ; -121.5,1704.21 2.41,1603.94
  lines w6: -1014.47,2168.38 -1014.47,2921.66 cw(c-974.8,2921.66) -974.8,2961.33 1621.53,2961.33 cw(c1621.53,2927.33) 1655.53,2927.33 ; -1014.47,2170.33 ccw(c-980.47,2170.33) -980.47,2136.33 ; -984,2136.33 1611,2135.65 ; -955.69,2768.65 1594.31,2768.65 ; -951,2868 1599,2868 ; 1609.01,2135.65 ccw(c1609.01,2181.89) 1655.25,2181.89 ; 1655.53,2181.89 1655.53,2926.33
  text "6 Layers Stack Up" at -210,2893 h57
  text "FAB NOTES:" at 1947.32,2890.98 h60
  text "Layer" at -951,2828 h24
  text "Gerber" at -51,2828 h24
  text "Copper" at 609,2828 h24
  text "Dielectric" at 1109,2828 h24
  text "Name" at -951,2788 h24
  text "Document" at -51,2788 h24
  text "Thickness" at 609,2788 h24
  text "Material" at 1109,2788 h24
  text "1. Materials: Green clad, FR-4/Epoxy class,or equivalent.dielectric costant 4.2+/-0.2 ," at 2055,2745 h60
  text "Top Solder Mask" at -951,2708 h34
  text "(.GTS)" at -51,2708 h34
  text "0.5mil" at 749,2708 h34
  text "Solder Resist" at 1109,2708 h34
  text "Top" at -951,2628 h34
  text "(.GTL)" at -51,2628 h34
  text "1.58mil" at 469,2628 h34
  text "see cross section for board thickness, copper" at 2215,2625 h60
  text "3.5mil" at 749,2588 h34
  text "FR4" at 1109,2588 h34
  text "GND_IN2" at -951,2548 h34
  text "(.GP1)" at -51,2548 h34
  text "0.65mil" at 469,2548 h34
  text "2.5mil" at 749,2508 h34
  text "FR4" at 1109,2508 h34
  text "weight and layer structures." at 2215,2505 h60
  text "SIG1_IN3" at -951,2468 h34
  text "(.G1)" at -51,2468 h34
  text "0.65mil" at 469,2468 h34
  text "2.5mil" at 749,2428 h34
  text "FR4" at 1109,2428 h34
  text "SIG2_IN4" at -951,2388 h34
  text "(.G2)" at -51,2388 h34
  text "0.65mil" at 469,2388 h34
  text "2. Components on the top and bottom layers." at 2035,2385 h60
  text "2.5mil" at 749,2348 h34
  text "FR4" at 1109,2348 h34
  text "PWR_IN5" at -951,2308 h34
  text "(.GP2)" at -51,2308 h34
  text "0.65mil" at 469,2308 h34
  text "3.5mil" at 749,2268 h34
  text "FR4" at 1109,2268 h34
  text "3. Minimum signal trace width/spacing : 4/5 mils." at 2035,2265 h60
  text "Bottom" at -951,2228 h34
  text "(.GBL)" at -51,2228 h34
  text "1.58mil" at 469,2228 h34
  text "Bottom Solder Mask" at -951,2148 h34
  text "(.GBS)" at -51,2148 h34
  text "0.5mil" at 749,2148 h34
  text "Solder Resist" at 1109,2148 h34
  text "4. Drilling:" at 2035,2145 h60
  text "4.1  minimum hole size is 6 mils drill." at 2195,2025 h60
  text "Overall Thickness :21.26 mil+/-10%" at -435,2011 h50
  text "4.2  all plated holes are to be plated thru and with min .001 thick." at 2195,1905 h60
  text "4.3  all hole diameters are finished sizes." at 2195,1785 h60
  text "R0.5" at -429.14,1692.92 h31
  text "5X" at -500.01,1688.98 h31
  text "2.6" at 106.29,1681.11 h31 r90
  text "14.2" at 565.74,1680.11 h31 r90
  text "4.4  all holes to be +/-0.003 from true position unless" at 2195,1665 h60
  text "41" at 727,1599 h31
  text "otherwise specified for PTH, or +/-0.002 if it's NPTH." at 2415,1565 h60
  text "4.5  NC drill file has been supplied, see hole size table." at 2195,1445 h60
  text "36.28" at 712,1418 h31
  text "5. Front to back pattern shall register within .005\"." at 2035,1325 h60
  text "6. Layer to layer(pattern to pattern) registration to be +/-.005\"." at 2035,1205 h60
  text "7. Soldermask: Both sides of board, Liquid Photo Imageable, soldermask" at 2035,1085 h60
  text "over bare copper (SMOBC), green." at 2206,960 h60
  text "8. Warpage and twist to meet IPC class II." at 2035,845 h60
  text "9. Silkscreen using white non-conductive epoxy or eqv." at 2035,725 h60
  text "10. Finish:" at 1995,585 h60
  text "10.1  Edge to be free of loose sliver and rough edge." at 2195,465 h60
  text "10.2  Finished board shall not have nicks scratches, voids," at 2195,345 h60
  text "exposed copper, poor plating or misdrilled holes." at 2526,240 h60
  text "10.3  Trace width tol=+/-.001\" of finished trace width." at 2195,125 h60
  text "0.95" at 744,24 h31
  text "11. Date code and UL rating shall be permanently marked or etched on PCB." at 1995,5 h60
  text "0" at -133.56,-15.49 h31
  text "12. Remove non-functional pad on all inner layers and planes" at 1995,-115 h60
  text "unit:mm" at 87.8,-119.61 h63
  text "0" at -11.51,-145.41 h31
  text "14.3" at 580,-145 h31 r90
  text "15.48" at 675.98,-151.72 h31 r90
  text "13. Impedance control:" at 1996,-260 h60
  text "13.1 Differential pairs:" at 2206,-400 h60
  text "FAB DRAWING" at -39.37,-452.76 h75
  text "4/8 mils width/gap on top and bottom layers should be controlled 100 ohms +/- 10% ." at 2225,-545 h60
  text "13.2 Single ended signals:" at 2226,-695 h60
  text "5 mils width on top layer should be controlled 50 ohms +/-10% ." at 2304,-842 h60
  text "14. This board use Via-in-Pad design for U3 component." at 1994,-975 h60
  text ".Legend" at -82,-1702 h60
